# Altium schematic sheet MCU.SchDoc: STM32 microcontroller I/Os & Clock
size A4; Date: Not used; ApprovedBy: Not used; CheckedBy: Not used; Author: Not used; CompanyName: STMicroelectronics; DrawnBy: Not used; Engineer: Not used; Organization: Not used; Address1: Not used; Address2: Not used; Address3: Not used; Address4: Not used; DocumentNumber: Not used; Revision: Not used; SheetNumber: 3; SheetTotal: 4
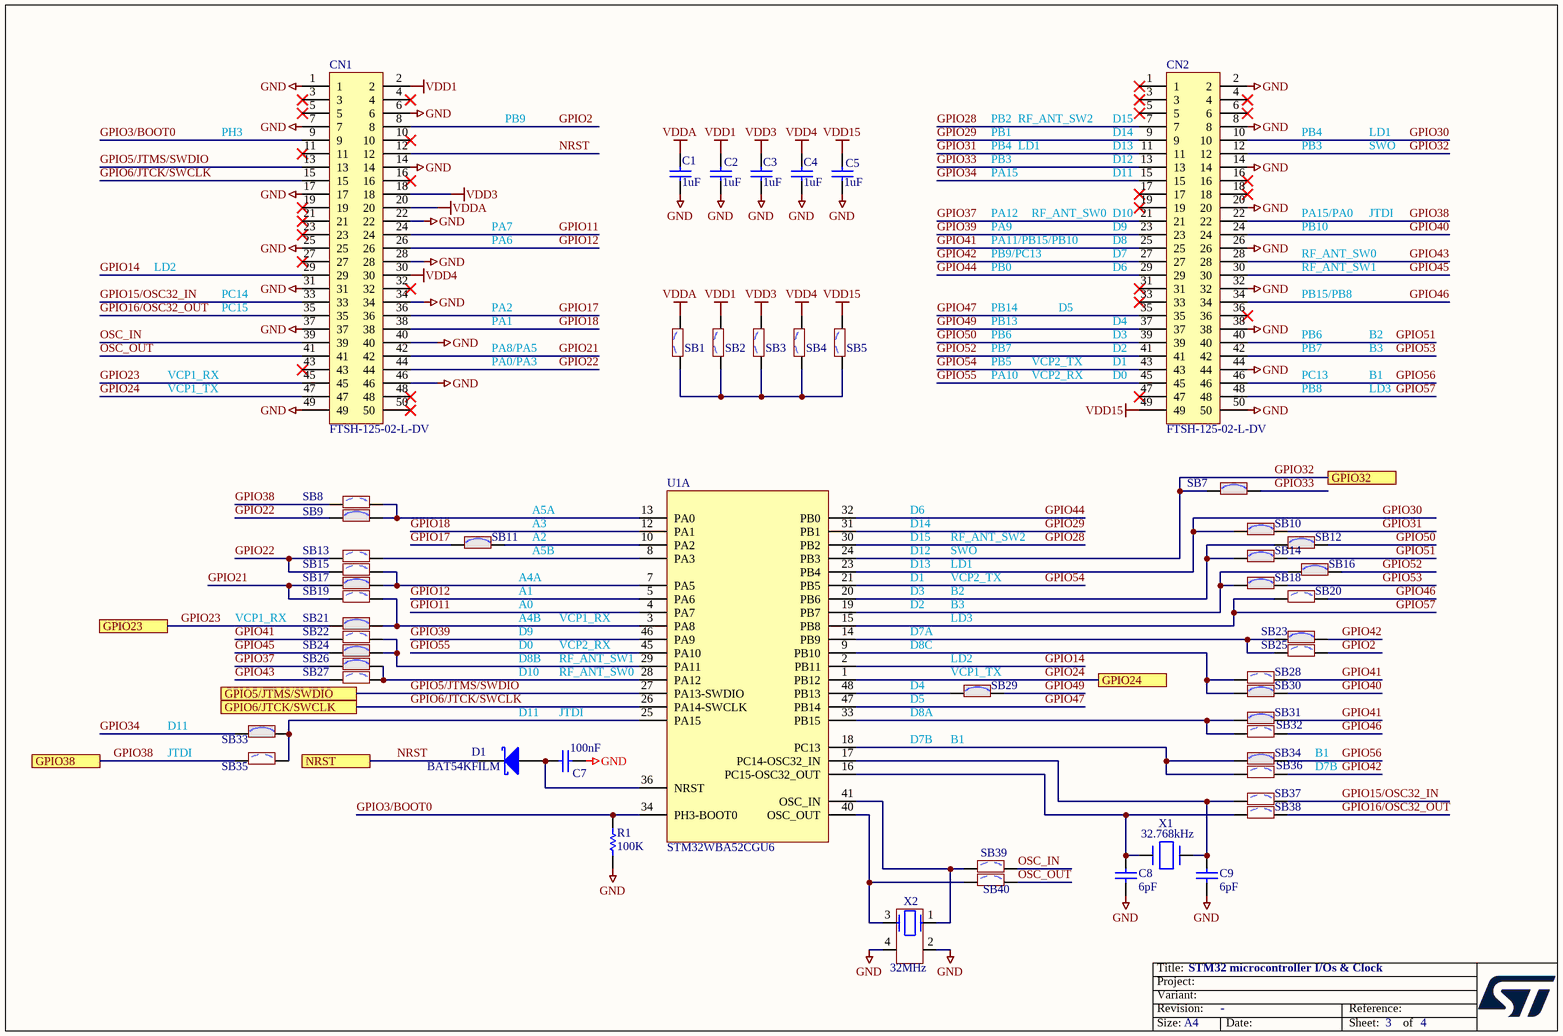
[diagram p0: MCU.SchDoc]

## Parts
C1  value 1uF  [C0402]  (hidden comment: Capacitor)
C2  value 1uF  [C0402]  (hidden comment: Capacitor)
C3  value 1uF  [C0402]  (hidden comment: Capacitor)
C4  value 1uF  [C0402]  (hidden comment: Capacitor)
C5  value 1uF  [C0402]  (hidden comment: Capacitor)
C7  value 100nF  [C0402]  (hidden comment: Capacitor)
C8  value 6pF  [C0402]  (hidden comment: Capacitor)
C9  value 6pF  [C0402]  (hidden comment: Capacitor)
CN1  FTSH-125-02-L-DV  [FTSH-125-02-L-DV]
CN2  FTSH-125-02-L-DV  [FTSH-125-02-L-DV]
D1  value BAT54KFILM  [DIO_SOD523_1A_2K]  (hidden comment: SCHOTTKY_1A_2K)
R1  value 100K  [R0402]  (hidden comment: Resistor)
SB1  SB_OFF  [SOLDER-BRIDGE_R0402-0R]  (value not drawn)
SB2  SB_OFF  [SOLDER-BRIDGE_R0402-0R]  (value not drawn)
SB3  SB_OFF  [SOLDER-BRIDGE_R0402-0R]  (value not drawn)
SB4  SB_OFF  [SOLDER-BRIDGE_R0402-0R]  (value not drawn)
SB5  SB_OFF  [SOLDER-BRIDGE_R0402-0R]  (value not drawn)
SB7  SB_ON  [SOLDER-BRIDGE_R0402-0R]  (value not drawn)
SB8  SB_OFF  [SOLDER-BRIDGE_R0402-0R]  (value not drawn)
SB9  SB_ON  [SOLDER-BRIDGE_R0402-0R]  (value not drawn)
SB10  SB_ON  [SOLDER-BRIDGE_R0402-0R]  (value not drawn)
SB11  SB_ON  [SOLDER-BRIDGE_R0402-0R]  (value not drawn)
SB12  SB_ON  [SOLDER-BRIDGE_R0402-0R]  (value not drawn)
SB13  SB_OFF  [SOLDER-BRIDGE_R0402-0R]  (value not drawn)
SB14  SB_ON  [SOLDER-BRIDGE_R0402-0R]  (value not drawn)
SB15  SB_OFF  [SOLDER-BRIDGE_R0402-0R]  (value not drawn)
SB16  SB_ON  [SOLDER-BRIDGE_R0402-0R]  (value not drawn)
SB17  SB_ON  [SOLDER-BRIDGE_R0402-0R]  (value not drawn)
SB18  SB_ON  [SOLDER-BRIDGE_R0402-0R]  (value not drawn)
SB19  SB_OFF  [SOLDER-BRIDGE_R0402-0R]  (value not drawn)
SB20  SB_OFF  [SOLDER-BRIDGE_R0402-0R]  (value not drawn)
SB21  SB_ON  [SOLDER-BRIDGE_R0402-0R]  (value not drawn)
SB22  SB_OFF  [SOLDER-BRIDGE_R0402-0R]  (value not drawn)
SB23  SB_ON  [SOLDER-BRIDGE_R0402-0R]  (value not drawn)
SB24  SB_ON  [SOLDER-BRIDGE_R0402-0R]  (value not drawn)
SB25  SB_OFF  [SOLDER-BRIDGE_R0402-0R]  (value not drawn)
SB26  SB_ON  [SOLDER-BRIDGE_R0402-0R]  (value not drawn)
SB27  SB_OFF  [SOLDER-BRIDGE_R0402-0R]  (value not drawn)
SB28  SB_OFF  [SOLDER-BRIDGE_R0402-0R]  (value not drawn)
SB29  SB_ON  [SOLDER-BRIDGE_R0402-0R]  (value not drawn)
SB30  SB_ON  [SOLDER-BRIDGE_R0402-0R]  (value not drawn)
SB31  SB_ON  [SOLDER-BRIDGE_R0402-0R]  (value not drawn)
SB32  SB_OFF  [SOLDER-BRIDGE_R0402-0R]  (value not drawn)
SB33  SB_ON  [SOLDER-BRIDGE_R0402-0R]  (value not drawn)
SB34  SB_ON  [SOLDER-BRIDGE_R0402-0R]  (value not drawn)
SB35  SB_OFF  [SOLDER-BRIDGE_R0402-0R]  (value not drawn)
SB36  SB_OFF  [SOLDER-BRIDGE_R0402-0R]  (value not drawn)
SB37  SB_OFF  [SOLDER-BRIDGE_R0402-0R]  (value not drawn)
SB38  SB_OFF  [SOLDER-BRIDGE_R0402-0R]  (value not drawn)
SB39  SB_OFF  [SOLDER-BRIDGE_R0402-0R]  (value not drawn)
SB40  SB_OFF  [SOLDER-BRIDGE_R0402-0R]  (value not drawn)
U1  STM32WBA52CGU6  [ICC_UFQFPN48-EPAD_7X7_H0P55_P050]  (part A of 3)
X1  value 32.768kHz  [CRY_NX1610SE_2P]  (hidden comment: XTAL_2_PINS)
X2  value 32MHz  [CRY_NX1612SA_4P]  (hidden comment: XTAL_4_PINS)

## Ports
GPIO5/JTMS/SWDIO, GPIO6/JTCK/SWCLK, GPIO23, GPIO24, GPIO32, GPIO38, NRST

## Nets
GND: C1.1 C2.1 C3.1 C4.1 C5.1 C7.1 C8.1 C9.1 CN1.1 CN1.6 CN1.7 CN1.14 CN1.17 CN1.22 CN1.25 CN1.28 CN1.31 CN1.34 CN1.37 CN1.40 CN1.46 CN1.49 CN2.2 CN2.8 CN2.14 CN2.20 CN2.26 CN2.32 CN2.38 CN2.44 CN2.50 R1.2 X2.2 X2.4
VDD1: C2.2 CN1.2 SB2.2
VDD3: C3.2 CN1.18 SB3.2
VDD4: C4.2 CN1.30 SB4.2
VDD15: C5.2 CN2.49 SB5.2
VDDA: C1.2 CN1.20 SB1.2
GPIO2: CN1.8 SB25.2
GPIO3/BOOT0: CN1.9 R1.1 U1.34(PH3-BOOT0)
GPIO5/JTMS/SWDIO: CN1.13 U1.27(PA13-SWDIO) ; port GPIO5/JTMS/SWDIO
GPIO6/JTCK/SWCLK: CN1.15 U1.26(PA14-SWCLK) ; port GPIO6/JTCK/SWCLK
GPIO11: CN1.24 U1.4(PA7)
GPIO12: CN1.26 U1.5(PA6)
GPIO14: CN1.29 U1.2(PB11)
GPIO15/OSC32_IN: CN1.33 SB37.2
GPIO16/OSC32_OUT: CN1.35 SB38.2
GPIO17: CN1.36 SB11.1
GPIO18: CN1.38 U1.12(PA1)
GPIO21: CN1.42 SB17.1 SB19.1
GPIO22: CN1.44 SB9.1 SB13.1 SB15.1
GPIO23: CN1.45 SB21.1 ; port GPIO23
GPIO24: CN1.47 U1.1(PB12) ; port GPIO24
GPIO28: CN2.7 U1.30(PB2)
GPIO29: CN2.9 U1.31(PB1)
GPIO30: CN2.10 SB10.1 U1.23(PB4)
GPIO31: CN2.11 SB10.2
GPIO32: CN2.12 SB7.1 U1.24(PB3) ; port GPIO32
GPIO33: CN2.13 SB7.2
GPIO34: CN2.15 SB33.1
GPIO37: CN2.21 SB26.1
GPIO38: CN2.22 SB8.1 SB35.1 ; port GPIO38
GPIO39: CN2.23 U1.46(PA9)
GPIO40: CN2.24 SB30.2
GPIO41: CN2.25 SB22.1 SB28.2 SB31.2
GPIO42: CN2.27 SB23.2 SB36.2
GPIO43: CN2.28 SB27.1
GPIO44: CN2.29 U1.32(PB0)
GPIO45: CN2.30 SB24.1
GPIO46: CN2.34 SB20.2 SB32.2
GPIO47: CN2.35 U1.47(PB14)
GPIO49: CN2.37 SB29.2
GPIO50: CN2.39 SB12.2
GPIO51: CN2.40 SB14.2
GPIO52: CN2.41 SB16.2
GPIO53: CN2.42 SB18.2
GPIO54: CN2.43 U1.21(PB5)
GPIO55: CN2.45 U1.45(PA10)
GPIO56: CN2.46 SB34.2
GPIO57: CN2.48 SB20.1 U1.15(PB8)
NRST: CN1.12 D1.2(K) ; port NRST
OSC_IN: CN1.39 SB39.2
OSC_OUT: CN1.41 SB40.2
NetC7_2: C7.2 D1.1(A) U1.36(NRST)
NetC8_2: C8.2 SB38.1 U1.16(PC15-OSC32_OUT) X1.2(X2)
NetC9_2: C9.2 SB37.1 U1.17(PC14-OSC32_IN) X1.1(X1)
NetSB1_1: SB1.1 SB2.1 SB3.1 SB4.1 SB5.1
NetSB8_2: SB8.2 SB9.2 U1.13(PA0)
NetSB11_2: SB11.2 U1.10(PA2)
NetSB12_1: SB12.1 SB14.1 U1.20(PB6)
NetSB13_2: SB13.2 U1.8(PA3)
NetSB15_2: SB15.2 SB17.2 U1.7(PA5)
NetSB16_1: SB16.1 SB18.1 U1.19(PB7)
NetSB19_2: SB19.2 SB21.2 U1.3(PA8)
NetSB22_2: SB22.2 SB24.2 U1.29(PA11)
NetSB23_1: SB23.1 SB25.1 U1.14(PB9)
NetSB26_2: SB26.2 SB27.2 U1.28(PA12)
NetSB28_1: SB28.1 SB30.1 U1.9(PB10)
NetSB29_1: SB29.1 U1.48(PB13)
NetSB31_1: SB31.1 SB32.1 U1.33(PB15)
NetSB33_2: SB33.2 SB35.2 U1.25(PA15)
NetSB34_1: SB34.1 SB36.1 U1.18(PC13)
NetSB39_1: SB39.1 U1.41(OSC_IN) X2.1
NetSB40_1: SB40.1 U1.40(OSC_OUT) X2.3

Not connected (* = marked no-connect by the designer): CN1 3* 4* 5* 10* 11* 16* 19* 21* 23* 27* 32* 43* 48* 50*; CN2 1* 3* 4* 5* 6* 16* 17* 18* 19* 31* 33* 36* 47*

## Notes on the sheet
- PH3
- PB9
- PB1
- PB2
- PB3
- PB4
- PA15
- LD1
- RF_ANT_SW2
- (near CN2) D11
- (near CN2) D13
- (near CN2) D14
- (near CN2) D15
- (near CN2) D12
- SWO
- PA6
- PA7
- PA9
- PA11/PB15/PB10
- PA12
- RF_ANT_SW0
- (near CN2) D10
- (near CN2) D9
- (near CN2) D8
- PA15/PA0
- PB10
- JTDI
- LD2
- PC14
- PC15
- PA2
- PB14
- PB0
- PB9/PC13
- D5
- (near CN2) D7
- (near CN2) D6
- RF_ANT_SW1
- PB15/PB8
- VCP1_RX
- PA0/PA3
- PA8/PA5
- PA1
- PB13
- PA10
- PB5
- PB6
- PB7
- VCP2_TX
- VCP2_RX
- (near CN2) D1
- (near CN2) D4
- (near CN2) D3
- (near CN2) D2
- (near CN2) D0
- PC13
- B1
- B2
- B3
- VCP1_TX
- PB8
- LD3
- (near SB11) A5A
- D6
- (near SB11) A4A
- (near SB11) A3
- (near SB11) A2
- (near SB11) A5B
- D12
- D1
- D13
- D15
- D14
- A4B
- A0
- (near SB11) A1
- D0
- D9
- D8C
- D7A
- D2
- D3
- D11
- D10
- D8B
- (near U1) RF_ANT_SW1
- (near U1) RF_ANT_SW0
- (near SB29) D8A
- (near SB29) D5
- (near SB29) D4
- (near SB29) VCP1_TX
- (near SB29) LD2
- D7B
- (near SB29) B1

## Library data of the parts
C1-C5 = MCD-01722: Capacitor, MLCC, 1uF, 10V, X5R, +/-10%, 0402, T=0.5mm; Part_Preference: Recommended; Manufacturer: YAGEO; Manufacturer_Part_Number: CC0402KRX5R6BB105; Component_Country_Of_Origin: China
C7 = MCD-00006: Capacitor, MLCC, 100nF, 16V, X7R, +/-10%, 0402, T=0.5mm; Manufacturer_Part_Number: CC0402KRX7R7BB104; Manufacturer: YAGEO; Alternate_Manufacturer_Part_Number: GCM155R71C104KA55D; Alternate_Manufacturer: MURATA; Part_Preference: Recommended; Order_Code_RS: 616-9701
C8 C9 = MCD-03185: 6 pF ±0,25pF 50V Condensateurs céramique C0G, NP0 0402 (1005 métrique); Part_Preference: Recommended; Manufacturer: MURATA; Manufacturer_Part_Number: GJM1555C1H6R0CB01; Order_Code_RS: 170-6040; ShowFields: YES; ID: 5301; Component_Country_Of_Origin: Singapore
CN1 CN2 = MCD-02746: Header, 25x2, 12.7mm, VR, SMD, T=4.83mm; Part_Type: Connector; Part_Preference: Recommended; Manufacturer: SAMTEC; Value: Header 25x2; Component_Country_Of_Origin: China, Costa Rica, Malaysia, USA, Vietnam; ShowFields: YES; ID: 4858
D1 = MCD-01677: Small signal Schottky diodes; Part_Type: Diode; Manufacturer: STMICROELECTRONICS; BMS_Part_Number: 9151123; Part_Preference: Recommended; Manufacturer_HQ_COO: EU
R1 = MCD-00059: Resistor, 100K, 0402, +/-1%, 1/16W; Part_Preference: Recommended; Manufacturer: YAGEO; Manufacturer_Part_Number: RC0402FR-07100KL; Component_Country_Of_Origin: China
SB1-SB5 SB8 SB13 SB15 SB19 SB20 SB22 SB25 SB27 SB28 SB32 SB35-SB40 = MCD-02162: Solder Bridge 0402 OFF; Part_Type: Misc; Part_Preference: Recommended; Manufacturer: YAGEO; Manufacturer_Part_Number: RC0402JR-070RL; Order_Code_RS: 618-5804; Component_Country_Of_Origin: China
SB7 SB9-SB12 SB14 SB16-SB18 SB21 SB23 SB24 SB26 SB29-SB31 SB33 SB34 = MCD-01618: Solder Bridge 0402 ON; Part_Type: Misc; Part_Preference: Recommended; Manufacturer: YAGEO; Manufacturer_Part_Number: RC0402JR-070RL; Order_Code_RS: 618-5804; Component_Country_Of_Origin: China
U1 = MCD-02741: MCU,ARM Cortex M33,1MB Flash, 128KB SRAM, Crypto, RF 2.4GHz, BLE, 802.15.4; Part_Type: IC; Part_Preference: Recommended; Manufacturer: STMICROELECTRONICS; ShowFields: YES; ID: 4853; Component_Country_Of_Origin: Unknown
X1 = MCD-02579: Crystal, 32.768kHz, 6pF, +/-20ppm, 70KR, 1.6x1mm; Part_Type: Crystal_Osc; Part_Preference: Recommended; Manufacturer: NDK; Manufacturer_Part_Number: NX1610SE-32.768KHZ-EXS00A-MU01501
X2 = MCD-02578: Crystal, 32MHz, 8pF, +/-10ppm, 40R, 1612(metric), T=0.3mm; Part_Type: Crystal_Osc; Part_Preference: Recommended; Manufacturer: NDK; Manufacturer_Part_Number: NX1612SA-32MHZ-EXS00A-CS09166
